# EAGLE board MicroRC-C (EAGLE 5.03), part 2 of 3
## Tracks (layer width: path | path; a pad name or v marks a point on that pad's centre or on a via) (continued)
CS_DTMF  (via drill 0.41) (continued)
  Top 0.178: U2.38 51.21,34.38 50.8,33.97 48.26,33.97 47.62,33.34 47.62,24.58 | v47.62,23.97 47.62,24.58 | v70.48,31.75 70.48,32.36 | 70.48,32.36 U6.10 | 47.62,24.58 47.35,24.14 v47.62,23.97 | 47.62,24.58 47.9,24.14 v47.62,23.97 | 70.48,32.36 70.21,31.92 v70.48,31.75 | 70.48,32.36 70.76,31.92 v70.48,31.75
  Bottom 0.178: 48.23,23.97 52.39,23.97 56.67,19.68 61.91,19.68 63.66,21.43 67.15,21.43 68.58,22.86 68.58,28.26 70.48,30.16 70.48,31.14 | 48.23,23.97 v47.62,23.97 | 70.48,31.14 v70.48,31.75 | 48.23,23.97 47.79,24.24 v47.62,23.97 | 48.23,23.97 47.79,23.7 v47.62,23.97 | 70.48,31.14 70.76,31.58 v70.48,31.75 | 70.48,31.14 70.21,31.58 v70.48,31.75
DISC_AUDIO
  Top 0.254: X3.6 144.46,58.42 146.05,56.83 146.05,49.21 146.72,48.54 R26.3 151.81,48.54 152.08,48.26 152.08,33.65 151.72,33.3 R27.3
  Bottom 0.61: X3.6 X3A.6
DTMF_Q1
  Top 0.178: 61.12,35.08 59.85,33.81 59.85,31.75 59.32,31.22 U2.29 | 61.12,35.08 | 61.12,35.08 71.6,35.08 71.75,34.92 U6.11
DTMF_Q2
  Top 0.178: U6.12 73.03,34.92 72.39,35.56 60.96,35.56 59.37,33.97 59.37,32.54 58.85,32.02 U2.30
DTMF_Q3
  Top 0.178: U6.13 74.3,34.92 73.18,36.04 60.8,36.04 58.9,34.13 58.9,33.34 58.38,32.82 U2.31
DTMF_Q4
  Top 0.178: U6.14 75.56,34.92 73.98,36.51 60.64,36.51 58.42,34.29 58.42,33.97 58.07,33.62 U2.32
EXP_IO0  (via drill 0.41)
  Top 0.178: v44.77,45.4 45.38,45.4 | 45.38,45.4 53.37,45.4 | 53.37,45.4 v53.98,45.4 | U2.4 45.61,24.55 45.09,25.08 45.09,27.01 | v45.09,27.62 45.09,27.01 | 53.37,45.4 53.81,45.13 v53.98,45.4 | 53.37,45.4 53.81,45.67 v53.98,45.4 | 45.09,27.01 45.36,27.46 v45.09,27.62 | 45.09,27.01 44.81,27.46 v45.09,27.62 | 45.38,45.4 44.93,45.67 v44.77,45.4 | 45.38,45.4 44.93,45.13 v44.77,45.4
  Bottom 0.178: v53.98,45.4 53.98,46.01 | 53.98,46.01 53.98,55.88 60.33,62.23 114.94,62.23 116.84,60.32 116.84,47.31 120.33,43.81 126.05,43.81 J2.15 | 45.09,28.23 45.09,33.34 44.13,34.29 44.13,43.81 44.77,44.45 44.77,44.79 | 45.09,28.23 v45.09,27.62 | 44.77,44.79 v44.77,45.4 | 53.98,46.01 53.7,45.57 v53.98,45.4 | 53.98,46.01 54.25,45.57 v53.98,45.4 | 45.09,28.23 44.81,27.79 v45.09,27.62 | 45.09,28.23 45.36,27.79 v45.09,27.62 | 44.77,44.79 45.04,45.24 v44.77,45.4 | 44.77,44.79 44.5,45.24 v44.77,45.4
EXP_IO1  (via drill 0.41)
  Top 0.178: v45.72,46.35 46.33,46.35 | 46.33,46.35 49.55,46.35 | 49.55,46.35 v50.16,46.35 | U2.5 46.41,24.71 46.04,25.08 46.04,26.06 | v46.04,26.67 46.04,26.06 | 49.55,46.35 50,46.08 v50.16,46.35 | 49.55,46.35 50,46.63 v50.16,46.35 | 46.04,26.06 46.31,26.5 v46.04,26.67 | 46.04,26.06 45.77,26.5 v46.04,26.67 | 46.33,46.35 45.88,46.63 v45.72,46.35 | 46.33,46.35 45.88,46.08 v45.72,46.35
  Bottom 0.178: J2.19 127.16,50.16 125.89,48.89 120.33,48.89 119.38,49.85 119.38,61.59 116.2,64.77 59.05,64.77 51.59,57.31 | 51.59,57.31 | 51.59,57.31 51.44,57.15 51.44,48.42 50.16,47.15 50.16,46.96 | v50.16,46.35 50.16,46.96 | v46.04,26.67 46.04,27.28 | 46.04,27.28 46.04,33.34 44.77,34.61 44.77,43.5 45.72,44.45 45.72,45.74 | 45.72,45.74 v45.72,46.35 | 50.16,46.96 49.89,46.52 v50.16,46.35 | 50.16,46.96 50.44,46.52 v50.16,46.35 | 46.04,27.28 45.77,26.84 v46.04,26.67 | 46.04,27.28 46.31,26.84 v46.04,26.67 | 45.72,45.74 45.99,46.19 v45.72,46.35 | 45.72,45.74 45.45,46.19 v45.72,46.35
EXP_IO2  (via drill 0.41)
  Top 0.178: U2.37 52.07,35.42 52.07,42.57 | 52.07,42.57 v52.07,43.18 | 52.07,42.57 52.34,43.01 v52.07,43.18 | 52.07,42.57 51.8,43.01 v52.07,43.18
  Bottom 0.178: v52.07,43.18 52.07,43.79 | 52.07,43.79 52.07,46.99 52.7,47.62 52.7,56.51 59.69,63.5 115.57,63.5 118.11,60.96 118.11,48.58 119.86,46.83 122.71,46.83 123.19,46.35 126.05,46.35 J2.17 | 52.07,43.79 51.8,43.35 v52.07,43.18 | 52.07,43.79 52.34,43.35 v52.07,43.18
EXT_COS  (via drill 0.41)
  Top 0.178: Q5.3 65.09,41.27 R18.1 62.23,40.96 59.98,40.96 | U2.34 54.41,40.44 54.81,40.84 | 54.81,40.84 v55.24,41.27 | v59.37,40.96 59.98,40.96 | 59.98,40.96 59.54,41.23 v59.37,40.96 | 59.98,40.96 59.54,40.69 v59.37,40.96 | 54.81,40.84 55.32,40.97 v55.24,41.27 | 54.81,40.84 54.94,41.35 v55.24,41.27
  Bottom 0.178: 58.76,40.96 57.78,40.96 57.47,41.27 55.85,41.27 | 58.76,40.96 v59.37,40.96 | v55.24,41.27 55.85,41.27 | 58.76,40.96 59.21,40.69 v59.37,40.96 | 58.76,40.96 59.21,41.23 v59.37,40.96 | 55.85,41.27 55.41,41.55 v55.24,41.27 | 55.85,41.27 55.41,41 v55.24,41.27
FAN
  Bottom 0.61: X3.2 X3A.2
  pour Top (isolate 0.61, rank 2, no thermals): 143.19,69.21 140.97,69.21 139.7,70.48 139.7,71.75 139.38,72.07 115.25,72.07 114.94,71.75 114.94,60.96 125.73,60.96 130.18,65.41 139.38,65.41 139.7,65.72 139.7,66.67 140.97,67.94 143.19,67.94
FAN_DRIVE  (via drill 0.41)
  Top 0.178: v63.5,46.35 63.5,46.96 | 63.5,46.96 R17.1 | U2.39 50.41,36.26 50.16,36.51 50.16,36.85 | 50.16,36.85 v50.16,37.46 | 63.5,46.96 63.23,46.52 v63.5,46.35 | 63.5,46.96 63.77,46.52 v63.5,46.35 | 50.16,36.85 50.44,37.3 v50.16,37.46 | 50.16,36.85 49.89,37.3 v50.16,37.46
  Bottom 0.178: 62.89,46.35 61.91,46.35 60.96,47.31 55.56,47.31 55.24,46.99 55.24,44.77 54.93,44.45 53.34,44.45 53.02,44.13 53.02,42.23 52.7,41.91 51.75,41.91 50.16,40.32 50.16,38.07 | 62.89,46.35 v63.5,46.35 | v50.16,37.46 50.16,38.07 | 62.89,46.35 63.33,46.08 v63.5,46.35 | 62.89,46.35 63.33,46.63 v63.5,46.35 | 50.16,38.07 49.89,37.63 v50.16,37.46 | 50.16,38.07 50.44,37.63 v50.16,37.46
GND  (via drill 0.41, 0.61)
  Top 0.178: C5.2 59.53,11.11 59.53,12.09 | 59.53,12.09 v59.53,12.7 | v83.98,42.23 | v83.98,42.23 | C12.1 15.53,13.97 | 15.53,13.97 v14.92,13.97 | U3.23 25.42,11.77 25.2,11.54 | 25.2,11.54 v24.77,11.11 | 59.53,12.09 59.8,12.53 v59.53,12.7 | 59.53,12.09 59.26,12.53 v59.53,12.7 | 15.53,13.97 15.09,14.24 v14.92,13.97 | 15.53,13.97 15.09,13.7 v14.92,13.97 | 25.2,11.54 24.69,11.42 v24.77,11.11 | 25.2,11.54 25.07,11.04 v24.77,11.11
  Top 0.254: U1.4 40.19,51.12 | 40.19,51.12 v40.8,51.12 | C9.2 49.87,54.93 | 49.87,54.93 v50.48,54.93 | 70.48,42.86 U6.9 | 75.56,42.86 U6.5 | U6.6 74.3,42.86 | U9.26 117.47,34.63 | 117.47,34.63 v117.47,35.24 | U2.22 58.2,25.62 58.31,25.51 | 58.31,25.51 v58.74,25.08 | U2.53 42.6,30.42 42.75,30.28 | v43.18,29.84 42.75,30.28 | U2.63 42.35,22.42 v42.86,21.91 | C7.2 64.77,29.21 65.76,29.21 | 65.76,29.21 v66.67,29.21 | 65.76,24.45 64.77,24.45 C6.2 | 65.76,24.45 v66.67,24.45 | v100.49,27.78 | C72.2 99.06,27.78 99.88,27.78 | 99.88,27.78 v100.49,27.78 | Q5.2 64.2,43.33 64.2,44.47 | 64.2,44.47 v64.2,45.08 | U8.12 85.09,42.23 84.59,42.23 | 84.59,42.23 v83.98,42.23 | U3.25 25.66,13.07 25.51,13.22 | 25.51,13.22 v25.08,13.65 | D2.A 69.37,41.27 69.53,41.43 69.53,42.25 | 69.53,42.25 v69.53,42.86 | 65.76,24.45 66.52,24.1 v66.67,24.45 | 65.76,24.45 66.52,24.79 v66.67,24.45 | 65.76,29.21 66.52,28.86 v66.67,29.21 | 65.76,29.21 66.52,29.56 v66.67,29.21 | 40.19,51.12 40.67,50.87 v40.8,51.12 | 40.19,51.12 40.67,51.37 v40.8,51.12 | 49.87,54.93 50.35,54.68 v50.48,54.93 | 49.87,54.93 50.35,55.18 v50.48,54.93 | 69.53,42.25 69.78,42.73 v69.53,42.86 | 69.53,42.25 69.28,42.73 v69.53,42.86 | 84.59,42.23 84.11,42.48 v83.98,42.23 84.11,41.98 84.59,42.23 | 99.88,27.78 100.36,27.53 v100.49,27.78 | 99.88,27.78 100.36,28.03 v100.49,27.78 | 64.2,44.47 64.45,44.96 v64.2,45.08 | 64.2,44.47 63.95,44.96 v64.2,45.08 | 117.47,34.63 117.72,35.11 v117.47,35.24 | 117.47,34.63 117.23,35.11 v117.47,35.24 | 58.31,25.51 58.47,25 v58.74,25.08 | 58.31,25.51 58.82,25.35 v58.74,25.08 | 42.75,30.28 42.91,29.76 v43.18,29.84 | 42.75,30.28 43.27,30.11 v43.18,29.84 | v42.86,21.91 42.6,21.82 42.43,22.34 42.95,22.17 v42.86,21.91
  Top 0.254: 25.51,13.22 25.35,13.74 v25.08,13.65 | 25.51,13.22 25,13.39 v25.08,13.65
  Top 0.406: 34.11,30.96 C2.2 | 34.11,30.96 v33.5,30.96 | v69.53,42.86 70.14,42.86 | 70.14,42.86 70.48,42.86 | 74.3,42.86 75.56,42.86 | U6.5 75.56,43.84 | 75.56,43.84 v75.56,44.45 | v116.2,40.96 116.2,41.57 | 116.2,41.57 U9.4 | U9.26 117.47,32.36 | 117.47,32.36 v117.47,31.75 | v79.06,26.67 79.67,26.67 | 79.67,26.67 81.28,26.67 C74.- | C22.2 32.09,11.11 | 32.09,11.11 v32.7,11.11 | 91.44,45.38 v91.44,44.77 | 91.44,45.38 C53.2 | 101.6,45.38 v101.6,44.77 | 101.6,45.38 C54.2 | C73.2 78.45,29.53 | 78.45,29.53 v79.06,29.53 | Q1.2 | 34.11,30.96 33.56,31.15 v33.5,30.96 | 34.11,30.96 33.56,30.76 v33.5,30.96 | 32.09,11.11 32.63,10.92 v32.7,11.11 | 32.09,11.11 32.63,11.3 v32.7,11.11 | 70.14,42.86 69.6,43.05 v69.53,42.86 | 70.14,42.86 69.6,42.67 v69.53,42.86 | 75.56,43.84 75.76,44.38 v75.56,44.45 | 75.56,43.84 75.37,44.38 v75.56,44.45 | 116.2,41.57 116.01,41.02 v116.2,40.96 | 116.2,41.57 116.4,41.02 v116.2,40.96 | 117.47,32.36 117.28,31.82 v117.47,31.75 | 117.47,32.36 117.67,31.82 v117.47,31.75 | 79.67,26.67 79.12,26.86 v79.06,26.67 | 79.67,26.67 79.12,26.48 v79.06,26.67 | 91.44,45.38 91.25,44.83 v91.44,44.77 | 91.44,45.38 91.63,44.83 v91.44,44.77 | 101.6,45.38 101.41,44.83 v101.6,44.77 | 101.6,45.38 101.79,44.83 v101.6,44.77 | 78.45,29.53 78.99,29.34 v79.06,29.53 | 78.45,29.53 78.99,29.72 v79.06,29.53
  Top 0.61: v62.87,15.24 C1.2 | Q2.3 42.95,48.49 41.91,49.53 v38.73,49.53 | v20.32,30.64 Q1.2
  Top 0.813: U4.4 118.43,48.1 | 118.43,48.1 U4.2 | 118.43,48.1
  Top 1.27: C3.- v71.12,20.95
  Bottom 0.254: J2.6 121.6,32.38 118.75,35.24 118.08,35.24 | v117.47,35.24 118.08,35.24 | 118.08,35.24 117.6,35.49 v117.47,35.24 | 118.08,35.24 117.6,34.99 v117.47,35.24
  other vias: 107.63,27.46 69.61,52.39 74.22,52.39 113.98,46.67 113.98,45.4 32.46,52.39 32.46,56.2 89.22,69.21 89.22,67.94 2.22,74.29
  pour GROUND (isolate 0.305, rank 2, no thermals): 0.95,75.88 0.95,52.7 5.71,52.7 6.03,52.39 6.03,49.85 5.71,49.53 0.95,49.53 0.95,0.95 69.22,0.95 69.22,11.11 arc-90 70.48,12.38 74.45,12.38 arc90 75.09,13.02 75.09,23.81 arc-90 76.36,25.08 82.23,25.08 arc90 82.87,25.72 82.87,27.62 arc-180 85.41,27.62 85.41,25.72 arc90 86.04,25.08 100.33,25.08 arc90 100.97,25.72 100.97,26.19 arc-90 102.23,27.46 111.76,27.46 arc90 112.39,28.1 112.39,31.75 arc-90 113.67,32.86 113.67,32.86 arc-90 114.94,31.59 114.94,28.89 arc90 115.57,28.26 121.6,28.26 arc90 122.24,28.89 122.24,30.48 arc-90 123.51,31.75 124.78,31.75 arc90 125.41,32.38 arc90 124.78,33.02 123.51,33.02 arc-90 122.24,34.29 122.24,46.51 arc90 121.6,47.15 113.98,47.15 arc90 113.35,46.2 113.35,44.45 arc-90 112.08,43.18 106.05,43.18 arc-90 104.78,44.45 104.78,46.35 arc90 104.14,46.99 81.92,46.99 arc-90 80.64,48.26 80.64,60.64 arc-90 81.92,61.91 91.76,61.91 arc90 92.39,62.55 92.39,75.88
  pour Top (isolate 0.406, no thermals): 62.55,25.4 62.55,28.26 66.04,28.26 66.04,30.32 70.64,30.32 70.64,23.34 66.04,23.34 66.04,25.4
  pour Top (isolate 0.406, no thermals): 28.26,56.67 28.26,51.91 34.92,51.91 34.92,56.67
  pour Top (isolate 0.406, no thermals): 69.06,46.99 74.77,46.99 74.77,57.15 69.06,57.15
  pour Top (isolate 0.61, no thermals): 120.17,44.77 109.22,44.77 109.22,47.62 114.3,47.62 114.62,47.94 114.62,50.16 114.94,50.48 120.17,50.48 120.17,48.58 121.76,48.58 121.76,47.62 120.17,47.62
  pour Bottom (isolate 0.61, rank 6, no thermals): 0.64,75.25 34.29,75.25 34.29,28.57 33.34,27.62 33.34,23.02 33.97,22.38 43.18,22.38 43.18,20.16 41.12,18.1 21.91,18.1 20.95,17.14 20.95,5.4 21.91,4.44 31.11,4.44 31.43,4.76 31.43,5.71 31.75,6.03 32.7,6.03 33.02,5.71 33.02,4.76 33.34,4.44 37.47,4.44 37.78,4.76 37.78,6.35 42.23,6.35 42.23,4.76 42.55,4.44 52.7,4.44 52.7,6.98 52.39,7.3 51.44,7.3 51.12,7.62 51.12,8.25 51.44,8.57 57.78,8.57 58.1,8.25 58.1,7.62 57.78,7.3 56.83,7.3 56.52,6.98 56.52,4.44 68.58,4.44 68.58,6.98 68.26,7.3 67.31,7.3 66.99,7.62 66.99,8.25 67.31,8.57 69.37,8.57 69.37,1.59 0.64,1.59 0.64,49.53 5.71,49.53 6.03,49.85 6.03,52.39 5.71,52.7 0.64,52.7
  pour Bottom (no thermals): 9.84,72.39 9.84,69.21 3.81,69.21 3.81,59.69 0.95,59.69 0.95,72.39
  pour Top (isolate 0.305, no thermals): 104.14,25.88 104.14,27.94 109.86,27.94 109.86,27.15 107.79,27.15 106.52,25.88
  pour Top (no thermals): 88.58,67.31 88.58,69.85 90.49,69.85 91.12,69.21 91.12,67.94 90.49,67.31
  pour Top (isolate 0.61, rank 6, no thermals): 0.95,75.25 0.95,1.59 69.22,1.59 69.22,8.89 66.67,8.89 66.67,6.98 67.63,6.98 67.94,6.67 67.94,2.86 67.31,2.22 44.45,2.22 42.55,4.13 42.55,6.35 37.78,6.35 37.78,3.49 37.47,3.17 33.34,3.17 33.02,3.49 33.02,6.03 31.43,6.03 31.43,4.13 30.8,3.49 14.61,3.49 13.97,4.13 13.97,10.16 6.99,10.16 5.71,11.43 5.71,20.95 6.67,20.95 6.67,23.81 7.62,24.76 9.53,24.76 10.48,25.72 13.65,25.72 13.65,40.64 12.22,40.64 11.11,41.75 11.11,58.74 3.49,58.74 2.86,59.37 2.86,68.26 3.49,68.9 11.75,68.9 11.75,75.25
I2C_SCL  (via drill 0.41)
  Top 0.178: v46.04,52.39 46.65,52.39 | 46.65,52.39 46.99,52.39 47.31,52.7 R10.1 | U2.25 57.01,27.94 55.54,27.94 | v54.93,27.94 55.54,27.94 | 45.43,52.39 v46.04,52.39 | 45.43,52.39 U1.6 | v49.37,49.53 49.98,49.53 | 49.98,49.53 50.48,49.53 51.12,50.16 54.32,50.16 | 54.32,50.16 v54.93,50.16 | 55.54,27.94 55.09,28.21 v54.93,27.94 | 55.54,27.94 55.09,27.67 v54.93,27.94 | 46.65,52.39 46.2,52.66 v46.04,52.39 | 46.65,52.39 46.2,52.12 v46.04,52.39 | 45.43,52.39 45.87,52.12 v46.04,52.39 | 45.43,52.39 45.87,52.66 v46.04,52.39 | 54.32,50.16 54.76,49.89 v54.93,50.16 | 54.32,50.16 54.76,50.44 v54.93,50.16 | 49.98,49.53 49.54,49.8 v49.37,49.53 | 49.98,49.53 49.54,49.26 v49.37,49.53
  Bottom 0.178: 54.32,27.94 48.26,27.94 47.62,28.57 47.62,40.32 46.51,41.43 46.51,48.74 46.04,49.21 46.04,51.78 | 54.32,27.94 v54.93,27.94 | 46.04,51.78 v46.04,52.39 | J2.13 126.05,41.27 123.19,41.27 122.56,41.91 117.47,41.91 116.2,43.18 116.2,60.01 114.62,61.59 60.64,61.59 54.93,55.88 54.93,50.77 | v54.93,50.16 54.93,50.77 | 49.37,50.14 49.37,51.91 48.9,52.39 46.65,52.39 | 49.37,50.14 v49.37,49.53 | v46.04,52.39 46.65,52.39 | 54.32,27.94 54.76,27.67 v54.93,27.94 | 54.32,27.94 54.76,28.21 v54.93,27.94 | 46.04,51.78 46.31,52.22 v46.04,52.39 | 46.04,51.78 45.77,52.22 v46.04,52.39 | 46.65,52.39 46.2,52.66 v46.04,52.39 | 46.65,52.39 46.2,52.12 v46.04,52.39 | 54.93,50.77 54.66,50.33 v54.93,50.16 | 54.93,50.77 55.2,50.33 v54.93,50.16 | 49.37,50.14 49.1,49.69 v49.37,49.53 | 49.37,50.14 49.64,49.69 v49.37,49.53
I2C_SDA  (via drill 0.41)
  Top 0.178: v47.15,49.53 47.15,50.14 | 47.15,50.14 47.15,51.12 | 55.11,49.21 51.28,49.21 50.8,48.74 47.31,48.74 47.15,48.89 47.15,48.92 | 55.11,49.21 v55.72,49.21 | v47.15,49.53 47.15,48.92 | U2.26 57.01,28.89 56.17,28.89 | v55.56,28.89 56.17,28.89 | 47.15,50.14 46.88,49.69 v47.15,49.53 | 47.15,50.14 47.42,49.69 v47.15,49.53 | 47.15,48.92 47.42,49.36 v47.15,49.53 | 47.15,48.92 46.88,49.36 v47.15,49.53 | 56.17,28.89 55.73,29.16 v55.56,28.89 | 56.17,28.89 55.73,28.62 v55.56,28.89 | 55.11,49.21 55.56,48.94 v55.72,49.21 | 55.11,49.21 55.56,49.48 v55.72,49.21
  Top 0.254: U1.5 47.15,51.12 R11.1
  Bottom 0.178: 54.95,28.89 48.58,28.89 48.26,29.21 48.26,40.64 47.15,41.75 47.15,48.92 | 54.95,28.89 v55.56,28.89 | J2.11 126.05,38.73 123.19,38.73 121.92,40 118.43,40 115.57,42.86 115.57,59.69 114.3,60.96 60.96,60.96 55.72,55.72 55.72,49.82 | v55.72,49.21 55.72,49.82 | v55.72,49.21 | 47.15,48.92 v47.15,49.53 | 47.15,48.92 47.42,49.36 v47.15,49.53 | 47.15,48.92 46.88,49.36 v47.15,49.53 | 54.95,28.89 55.4,28.62 v55.56,28.89 | 54.95,28.89 55.4,29.16 v55.56,28.89 | 55.72,49.82 55.45,49.38 v55.72,49.21 | 55.72,49.82 55.99,49.38 v55.72,49.21
INT_DTMF  (via drill 0.41)
  Top 0.178: v76.83,35.4 76.83,34.79 | 76.83,34.79 U6.15 | U2.6 47.23,19.82 47.23,21.61 | v47.23,22.22 47.23,21.61 | 76.83,34.79 77.11,35.24 v76.83,35.4 | 76.83,34.79 76.56,35.24 v76.83,35.4 | 47.23,21.61 47.5,22.06 v47.23,22.22 | 47.23,21.61 46.96,22.06 v47.23,22.22
  Bottom 0.178: 47.84,22.22 53.18,22.22 56.36,19.05 62.23,19.05 63.98,20.8 67.47,20.8 69.22,22.54 69.22,27.94 71.75,30.48 71.75,34.45 72.71,35.4 76.22,35.4 | 47.84,22.22 v47.23,22.22 | 76.22,35.4 v76.83,35.4 | 76.22,35.4 76.67,35.13 v76.83,35.4 | 76.22,35.4 76.67,35.67 v76.83,35.4 | 47.84,22.22 47.39,22.5 v47.23,22.22 | 47.84,22.22 47.39,21.95 v47.23,22.22
INT_EXP  (via drill 0.41)
  Top 0.178: v49.21,40.32 48.6,40.32 | 48.6,40.32 47.94,40.32 47.31,40.96 R79.1 | U2.27 56.1,29.62 55.88,29.84 55.54,29.84 | v54.93,29.84 55.54,29.84 | 55.54,29.84 55.09,30.12 v54.93,29.84 | 55.54,29.84 55.09,29.57 v54.93,29.84 | 48.6,40.32 49.05,40.05 v49.21,40.32 | 48.6,40.32 49.05,40.59 v49.21,40.32
  Bottom 0.178: J2.18 120.33,47.62 118.75,49.21 118.75,61.28 115.89,64.13 59.37,64.13 52.07,56.83 52.07,47.94 51.12,46.99 51.12,42.23 49.64,40.75 | v49.21,40.32 49.64,40.75 | 49.21,39.71 49.21,30.16 49.53,29.84 54.32,29.84 | 49.21,39.71 v49.21,40.32 | 54.32,29.84 v54.93,29.84 | 54.32,29.84 54.76,29.57 v54.93,29.84 | 54.32,29.84 54.76,30.12 v54.93,29.84 | 49.64,40.75 49.14,40.63 v49.21,40.32 | 49.64,40.75 49.52,40.25 v49.21,40.32 | 49.21,39.71 49.48,40.16 v49.21,40.32 | 49.21,39.71 48.94,40.16 v49.21,40.32
INT_ISD  (via drill 0.41)
  Top 0.178: v81.92,35.4 81.92,36.01 | 81.92,36.01 81.92,36.19 arc0 82.23,36.51 100.33,36.51 100.97,37.15 115.89,37.15 116.2,36.83 U9.25 | R69.1 113.67,30.32 113.82,30.48 114.62,30.48 116.2,32.07 U9.25 | U2.7 48.02,19.82 48.02,20.5 | v48.02,21.11 48.02,20.5 | 48.02,20.5 48.29,20.95 v48.02,21.11 | 48.02,20.5 47.75,20.95 v48.02,21.11 | 81.92,36.01 81.64,35.57 v81.92,35.4 | 81.92,36.01 82.19,35.57 v81.92,35.4
  Top 0.254: U9.25
  Bottom 0.178: 81.31,35.4 78.74,35.4 77.63,34.29 73.03,34.29 72.39,33.65 72.39,30.16 69.85,27.62 69.85,22.22 67.79,20.16 64.29,20.16 62.55,18.41 56.04,18.41 53.34,21.11 48.63,21.11 | 81.31,35.4 v81.92,35.4 | 48.63,21.11 v48.02,21.11 | 48.63,21.11 48.19,21.38 v48.02,21.11 | 48.63,21.11 48.19,20.84 v48.02,21.11 | 81.31,35.4 81.75,35.13 v81.92,35.4 | 81.31,35.4 81.75,35.67 v81.92,35.4
INT_MX828  (via drill 0.41)
  Top 0.178: U8.7 91.44,40.64 91.12,40.32 83.19,40.32 82.55,40.96 82.21,40.96 | v81.6,40.96 82.21,40.96 | 67.63,32.99 67.63,33.65 67.31,33.97 63.18,33.97 62.87,33.65 R50.2 61.59,32.38 59.63,30.42 U2.28 | 67.63,32.99 v67.63,32.38 | 82.21,40.96 81.76,41.23 v81.6,40.96 | 82.21,40.96 81.76,40.69 v81.6,40.96 | 67.63,32.99 67.36,32.55 v67.63,32.38 | 67.63,32.99 67.9,32.55 v67.63,32.38
  Bottom 0.178: 80.99,40.96 68.58,40.96 67.63,40 67.63,32.99 | 80.99,40.96 v81.6,40.96 | v67.63,32.38 67.63,32.99 | 80.99,40.96 81.43,40.69 v81.6,40.96 | 80.99,40.96 81.43,41.23 v81.6,40.96 | 67.63,32.99 67.36,32.55 v67.63,32.38 | 67.63,32.99 67.9,32.55 v67.63,32.38
ISD_RAC  (via drill 0.41)
  Top 0.178: v114.94,36.19 114.94,35.58 | 114.94,35.58 U9.24 114.94,31.75 114.14,30.96 111.76,30.96 111.44,30.64 R70.1 | U2.9 49.61,20.71 48.42,21.91 48.42,25.74 | v48.42,26.35 48.42,25.74 | 114.94,35.58 115.21,36.03 v114.94,36.19 | 114.94,35.58 114.66,36.03 v114.94,36.19 | 48.42,25.74 48.69,26.19 v48.42,26.35 | 48.42,25.74 48.15,26.19 v48.42,26.35
  Bottom 0.178: 114.94,36.8 114.94,59.37 113.98,60.32 61.28,60.32 56.52,55.56 56.52,50.32 57.31,49.53 64.14,49.53 65.09,48.58 65.09,43.5 62.87,41.27 62.87,33.02 62.23,32.38 59.37,32.38 58.74,31.75 58.74,26.99 58.1,26.35 49.03,26.35 | 114.94,36.8 v114.94,36.19 | v48.42,26.35 49.03,26.35 | 114.94,36.8 114.66,36.36 v114.94,36.19 | 114.94,36.8 115.21,36.36 v114.94,36.19 | 49.03,26.35 48.58,26.62 v48.42,26.35 | 49.03,26.35 48.58,26.08 v48.42,26.35
LCD_BKLITE  (via drill 0.41)
  Top 0.178: v45.72,43.18 45.11,43.18 | 45.11,43.18 R9.1 | v45.72,43.18 | U2.1 43.21,18.76 43.02,18.57 43.02,18.39 | v43.02,17.78 43.02,18.39 | 43.02,18.39 42.75,17.95 v43.02,17.78 | 43.02,18.39 43.29,17.95 v43.02,17.78 | 45.11,43.18 45.55,42.91 v45.72,43.18 | 45.11,43.18 45.55,43.45 v45.72,43.18
  Bottom 0.178: 45.72,42.57 45.72,41.27 46.99,40 46.99,26.03 46.67,25.72 43.02,25.72 42.7,25.4 42.7,23.81 44.13,22.38 44.13,18.1 43.81,17.78 43.63,17.78 | 45.72,42.57 v45.72,43.18 | 43.63,17.78 v43.02,17.78 | 43.63,17.78 43.19,18.05 v43.02,17.78 | 43.63,17.78 43.19,17.51 v43.02,17.78 | 45.72,42.57 45.99,43.01 v45.72,43.18 | 45.72,42.57 45.45,43.01 v45.72,43.18
LCD_E
  Top 0.178: J1.6 21.59,36.19 20.64,37.15 20.64,47.94 21.27,48.58 29.69,48.58 30.64,47.62 30.64,39.21 30.96,38.89 46.51,38.89 48.81,36.59 U2.41
LCD_RS
  Top 0.178: J1.4 20.16,36.35 20.16,48.1 21.11,49.05 29.84,49.05 31.11,47.78 31.11,39.53 31.27,39.37 46.99,39.37 49.61,36.75 U2.40
LCD_RW
  Top 0.178: J1.5 24.13,37.46 21.75,37.46 21.11,38.1 21.11,47.78 | 21.11,47.78 21.43,48.1 29.53,48.1 30.16,47.47 30.16,39.05 30.8,38.42 46.04,38.42 48.01,36.44 U2.42 | 21.11,47.78
LED_PWR  (via drill 0.41)
  Top 0.178: v38.73,33.18 38.12,33.18 | 38.12,33.18 R8.1 | v41.75,35.24 42.18,34.81 | 42.18,34.81 43.02,33.97 46.99,33.97 47.21,34.19 U2.43 | 38.12,33.18 38.57,32.91 v38.73,33.18 | 38.12,33.18 38.57,33.45 v38.73,33.18 | 42.18,34.81 42.06,35.32 v41.75,35.24 | 42.18,34.81 41.68,34.93 v41.75,35.24
  Bottom 0.178: v41.75,35.24 41.14,35.24 | 41.14,35.24 39.37,35.24 38.73,34.61 38.73,33.79 | 38.73,33.79 v38.73,33.18 | 38.73,33.79 38.46,33.34 v38.73,33.18 | 38.73,33.79 39.01,33.34 v38.73,33.18 | 41.14,35.24 41.59,34.97 v41.75,35.24 | 41.14,35.24 41.59,35.51 v41.75,35.24
MIX_BUSS
  Top 0.254: R72.1 R76.2 R59.2 136.84,11.75 136.53,12.06 134.94,12.06 | 134.94,12.06 132.72,12.06 132.4,11.75 C51.1 | 134.94,12.06 R64.2 134.94,14.92 134.62,15.24 128.27,15.24 127.95,15.56 R51.2
MIX_INSERT  (via drill 0.41)
  Top 0.254: 121.6,19.07 C47.1 121.6,15.56 121.28,15.24 114.94,15.24 114.62,14.92 R16.1 | 121.6,19.07 v121.6,19.68 | J2.4 126.05,28.57 126.05,26.17 | v126.05,25.56 126.05,26.17 | 126.05,26.17 125.8,25.69 v126.05,25.56 | 126.05,26.17 126.3,25.69 v126.05,25.56 | 121.6,19.07 121.85,19.56 v121.6,19.68 | 121.6,19.07 121.35,19.56 v121.6,19.68
  Bottom 0.254: 125.44,25.56 122.71,25.56 121.6,24.45 121.6,20.29 | 125.44,25.56 v126.05,25.56 | v121.6,19.68 121.6,20.29 | 125.44,25.56 125.92,25.31 v126.05,25.56 | 125.44,25.56 125.92,25.81 v126.05,25.56 | 121.6,20.29 121.35,19.81 v121.6,19.68 | 121.6,20.29 121.85,19.81 v121.6,19.68
MUTE_AUX
  Top 0.178: U7.7 114.62,22.54 114.3,22.86 114.3,24.45 114.62,24.76 121.28,24.76 122.08,25.56 122.08,36.99 121.28,37.78 119.06,37.78 118.75,38.1 100.33,38.1 99.69,37.46 60.33,37.46 57.94,35.08 56.36,35.08 53.66,32.38 53.66,23.97 55.21,22.42 U2.18
MUTE_RX
  Top 0.178: U7.3 112.71,21.27 113.03,21.59 113.03,24.61 113.67,25.24 121.13,25.24 121.6,25.72 121.6,36.83 121.13,37.31 118.9,37.31 118.59,37.62 100.65,37.62 100.01,36.99 60.48,36.99 58.1,34.61 56.52,34.61 54.13,32.23 54.13,24.29 55.2,23.22 U2.19
N$1
  pour Top (isolate 0.61, no thermals): 4.13,67.31 4.45,67.63 11.43,67.63 12.7,66.36 12.7,64.77 4.45,64.77 4.13,65.09
N$2
  Top 0.254: C8.1 38.73,26.99 39.05,26.67 39.05,24.13 39.96,23.22 U2.62
  Top 0.406: C8.1
N$3
  Top 0.254: R82.2 C45.1
N$4  (via drill 0.41)
  Top 0.254: R26.2 146.69,46.04 146.05,45.4 146.05,39.69 144.78,38.42 144.78,34.26 | v144.78,33.65 144.78,34.26 | C39.2 106.7,20 | 106.7,20 v107.31,20 | 144.78,34.26 144.53,33.78 v144.78,33.65 | 144.78,34.26 145.03,33.78 v144.78,33.65 | 106.7,20 107.19,19.75 v107.31,20 | 106.7,20 107.19,20.25 v107.31,20
  Bottom 0.254: v107.31,20 107.31,20.61 | 107.31,20.61 107.31,20.95 107.63,21.27 114.3,21.27 114.62,20.95 114.62,16.19 114.94,15.87 117.16,15.87 119.06,17.78 136.53,17.78 137.16,18.41 137.16,20.64 138.75,22.22 138.75,26.03 139.38,26.67 139.38,27.94 138.75,28.57 138.75,32.7 139.7,33.65 144.17,33.65 | 144.17,33.65 v144.78,33.65 | 144.17,33.65 144.65,33.41 v144.78,33.65 | 144.17,33.65 144.65,33.9 v144.78,33.65 | 107.31,20.61 107.07,20.13 v107.31,20 | 107.31,20.61 107.56,20.13 v107.31,20
N$5  (via drill 0.41)
  Top 0.254: v138.11,13.65 138.11,14.26 | 138.11,14.26 138.11,14.6 138.75,15.24 139.06,15.24 139.38,15.56 C58.1 | 114.62,20 R62.1 | v113.67,20 114.28,20 | 114.28,20 114.62,20 | U7.6 114.94,21.27 114.62,20.95 114.62,20 | 114.28,20 113.79,20.25 v113.67,20 | 114.28,20 113.79,19.75 v113.67,20 | 138.11,14.26 137.86,13.78 v138.11,13.65 | 138.11,14.26 138.36,13.78 v138.11,13.65
  Bottom 0.254: 137.68,13.22 137.16,12.7 113.98,12.7 113.67,13.02 113.67,19.39 | 137.68,13.22 v138.11,13.65 | 113.67,19.39 v113.67,20 | 113.67,19.39 113.91,19.87 v113.67,20 | 113.67,19.39 113.42,19.87 v113.67,20 | 137.68,13.22 138.2,13.39 v138.11,13.65 | 137.68,13.22 137.85,13.74 v138.11,13.65
N$6
  Top 0.254: R64.1 136.84,14.92 137.16,15.24 137.48,15.24 138.11,15.87 138.11,18.1 138.43,18.41 143.83,18.41 144.78,19.37 144.78,31.75 145.73,32.7 145.73,37.94 146.21,38.42 R63.2
N$7
  Top 0.254: R65.2 136.84,20.16 136.84,20.32 138.02,21.49 R66.2
N$8
  Top 0.254: C63.2 102.23,31.43 102.55,31.75 104.46,31.75 104.78,32.07 U9.16
N$9
  Top 0.254: JP5.2 R12.2
N$10
  Top 0.254: U8.11 86.36,44.13 86.04,44.45 84.14,44.45 83.82,44.77 C56.+
N$11
  Top 0.254: R83.2 C52.1
N$12
  Top 0.254: R42.2 92.71,21.91 93.34,21.27 95.25,21.27 95.89,20.64 JP4.1
N$13
  pour Top (isolate 0.61, rank 3, no thermals): 18.73,46.67 16.51,46.67 16.51,48.89 17.46,49.85 17.46,56.83 19.05,58.42 19.05,71.12 20.64,71.12 20.64,62.86 21.91,61.59 26.35,61.59 26.35,56.2 21.91,56.2 20.95,55.24 20.95,50.16 18.73,47.94
N$14
  pour Top (isolate 0.61, no thermals): 12.7,63.5 12.7,61.91 10.79,60.01 4.45,60.01 4.13,60.32 4.13,63.18 4.45,63.5
N$15  (via drill 0.41)
  Top 0.254: C59.1 133.06,16.83 | 133.06,16.83 v133.67,16.83 | 134.28,16.83 v133.67,16.83 | 134.28,16.83 R65.1 | v138.11,20 138.72,20 | 138.72,20 R67.1 C60.1 | 133.06,16.83 133.54,16.58 v133.67,16.83 | 133.06,16.83 133.54,17.08 v133.67,16.83 | 134.28,16.83 133.8,17.08 v133.67,16.83 | 134.28,16.83 133.8,16.58 v133.67,16.83 | 138.72,20 138.24,20.25 v138.11,20 | 138.72,20 138.24,19.75 v138.11,20
  Bottom 0.254: v133.67,16.83 134.28,16.83 | 134.28,16.83 136.84,16.83 138.11,18.1 138.11,19.39 | 138.11,19.39 v138.11,20 | v138.11,20 138.72,20 | 138.72,20 TP8.TP | 134.28,16.83 133.8,17.08 v133.67,16.83 | 134.28,16.83 133.8,16.58 v133.67,16.83 | 138.11,19.39 138.36,19.87 v138.11,20 | 138.11,19.39 137.86,19.87 v138.11,20 | 138.72,20 138.24,20.25 v138.11,20 | 138.72,20 138.24,19.75 v138.11,20
N$16
  Top 0.178: U6.7 73.18,42.86
  Top 0.254: U6.7 | 73.18,42.86 Y2.2
N$17
  Top 0.178: Y2.1 | Y2.1
  Top 0.254: U6.8 71.75,44.13 Y2.1
N$18
  Top 0.178: U6.4 76.83,41.27 76.99,41.12 80.49,41.12 80.64,41.27 U6.1
N$19
  pour Top (isolate 0.61, rank 3, no thermals): 22.23,72.07 29.84,72.07 30.16,71.75 30.16,68.26 30.48,67.94 33.02,67.94 33.02,65.41 33.34,65.09 33.34,62.86 22.54,62.86 21.91,63.5 21.91,71.75
N$20
  Top 0.254: Y4.2 37.15,54.93 U1.1
N$21
  Top 0.254: Y4.1 37.15,53.66 U1.2
N$22
  Top 0.254: C61.1 R68.2
N$23
  Top 0.254: R76.1 144.15,10.48 146.05,12.38 147.48,12.38 149.86,14.76 149.86,16.35 148,18.22 R75.2
N$24
  Top 0.254: 114.62,5.71 115.57,5.71 115.89,6.03 115.89,6.35 116.2,6.67 U10.12 | 114.62,5.71 108.58,5.71 108.27,5.4 C65.1 | 114.62,5.71 R77.2 | 114.62,5.71 R73.1
N$25  (via drill 0.41)
  Top 0.254: C64.2 119.72,16.83 | 119.72,16.83 v120.33,16.83 | 119.72,16.83 120.2,16.58 v120.33,16.83 | 119.72,16.83 120.2,17.08 v120.33,16.83
  Bottom 0.254: v120.33,16.83 120.94,16.83 | 120.94,16.83 126.36,16.83 127.32,15.87 141.6,15.87 141.92,16.19 141.92,24.13 143.47,25.68 R75.3 | 120.94,16.83 120.46,17.08 v120.33,16.83 | 120.94,16.83 120.46,16.58 v120.33,16.83
N$26
  Top 0.254: U6.2 79.38,44.45 80.33,45.4 R45.2 79.06,46.67 78.74,46.99 78.74,48.58 | 78.74,48.58 78.74,51.91 78.42,52.23 77.15,52.23 C40.2 | R41.2 77.15,48.42 77.31,48.58 78.74,48.58
N$27  (via drill 0.41)
  Top 0.254: v89.53,26.35 89.53,26.96 | 89.53,26.96 C41.2 | 89.53,26.96 89.29,26.48 v89.53,26.35 | 89.53,26.96 89.78,26.48 v89.53,26.35
  Bottom 0.254: 90.14,26.35 90.49,26.35 90.81,26.03 JP4.3 | 90.14,26.35 v89.53,26.35 | 90.14,26.35 89.66,26.6 v89.53,26.35 | 90.14,26.35 89.66,26.1 v89.53,26.35
N$28
  Top 0.254: U6.3 78.11,44.45 77.15,45.4 R41.1 76.83,46.99 76.04,46.99 75.72,47.31 75.72,50.16 76.04,50.48 C40.1
N$29
  Top 0.254: R32.2 73.5,27.62 73.66,27.78 73.66,29.37 arc0 73.82,29.53 C30.1 74.93,30.48 75.25,30.8 79.06,30.8 79.38,31.11 U6.17
N$30
  Top 0.254: 60.64,28.1 60.64,29.05 60.96,29.37 62.87,29.37 C7.1 | 60.64,28.1 Y1.1 | U2.24 59.77,27.22 60.64,28.1
N$31  (via drill 0.41)
  Top 0.254: v36.2,6.35 36.2,5.74 | 36.2,5.74 R14.2 | 36.2,5.74 36.44,6.22 v36.2,6.35 | 36.2,5.74 35.95,6.22 v36.2,6.35
  Bottom 0.178: JP5.4 41.27,9.52 40.96,9.84 36.51,9.84 36.2,9.52 36.2,6.96 | 36.2,6.96 v36.2,6.35 | 36.2,6.96 35.92,6.52 v36.2,6.35 | 36.2,6.96 36.47,6.52 v36.2,6.35
N$32
  Top 0.254: U6.16 78.11,31.91 77.79,31.59 72.71,31.59 72.39,31.27 R32.1
N$33  (via drill 0.41)
  Top 0.254: v106.05,31.75 106.05,32.36 | 106.05,32.36 U9.17 | C59.2 129.38,16.83 129.22,16.99 129.22,18.12 | v129.22,18.73 129.22,18.12 | 106.05,32.36 105.8,31.88 v106.05,31.75 | 106.05,32.36 106.29,31.88 v106.05,31.75 | 129.22,18.12 129.47,18.6 v129.22,18.73 | 129.22,18.12 128.97,18.6 v129.22,18.73
  Bottom 0.254: 128.61,18.73 117.16,18.73 116.52,19.37 116.52,27.94 115.25,29.21 106.68,29.21 106.05,29.84 106.05,31.14 | 128.61,18.73 v129.22,18.73 | 106.05,31.14 v106.05,31.75 | 106.05,31.14 106.29,31.62 v106.05,31.75 | 106.05,31.14 105.8,31.62 v106.05,31.75 | 128.61,18.73 129.09,18.48 v129.22,18.73 | 128.61,18.73 129.09,18.98 v129.22,18.73
N$34
  Top 0.178: U3.3 18.1,13.72 C12.2
N$35
  Top 0.254: C44.2 107.31,13.65 107,13.33 107,7.62 107.31,7.3 R48.1
N$36
  Top 0.178: U3.27 29.53,14.37 C11.2
N$37  (via drill 0.41)
  Top 0.254: v102.23,33.02 102.23,33.63 | 102.23,33.63 102.23,35.58 | 102.23,35.58 v102.23,36.19 | v115.89,16.83 116.5,16.83 | 116.5,16.83 C64.1 | 116.5,16.83 116.02,17.08 v115.89,16.83 | 116.5,16.83 116.02,16.58 v115.89,16.83 | 102.23,35.58 102.48,36.07 v102.23,36.19 | 102.23,35.58 101.99,36.07 v102.23,36.19 | 102.23,33.63 101.99,33.15 v102.23,33.02 | 102.23,33.63 102.48,33.15 v102.23,33.02
  Top 0.406: v104.78,40.96 104.78,41.57 | 104.78,41.57 U9.13 | 104.78,41.57 104.58,41.02 v104.78,40.96 | 104.78,41.57 104.97,41.02 v104.78,40.96
  Bottom 0.254: 102.23,32.41 102.23,27.62 103.19,26.67 114.94,26.67 115.89,25.72 115.89,17.44 | 102.23,32.41 v102.23,33.02 | 115.89,17.44 v115.89,16.83 | 104.17,40.96 103.5,40.96 102.23,39.69 102.23,36.8 | 104.17,40.96 v104.78,40.96 | v102.23,36.19 102.23,36.8 | 104.17,40.96 104.65,40.71 v104.78,40.96 | 104.17,40.96 104.65,41.21 v104.78,40.96 | 115.89,17.44 115.64,16.96 v115.89,16.83 | 115.89,17.44 116.14,16.96 v115.89,16.83 | 102.23,36.8 101.99,36.32 v102.23,36.19 | 102.23,36.8 102.48,36.32 v102.23,36.19 | 102.23,32.41 102.48,32.89 v102.23,33.02 | 102.23,32.41 101.99,32.89 v102.23,33.02
N$38
  Top 0.254: C6.1 62.87,24.29 60.96,24.29 60.64,24.61 Y1.2 60.64,25.56 59.78,26.42 U2.23
N$39
  Top 0.178: U3.1 20.58,16.89 20.32,17.14 C13.1
N$40
  Top 0.254: R45.1 C43.2
N$41
  Top 0.254: U8.10 C55.+
N$42
  Top 0.254: C48.2 R56.1
N$43  (via drill 0.41)
  Top 0.254: 97.79,11.75 97.79,10.79 97.47,10.48 U5.6 94.75,10.48 | 97.79,11.75 97.79,16.51 98.11,16.83 R36.2 | 97.79,11.75 U5.7 | v94.14,10.48 94.75,10.48 | R30.2 78.42,5.1 | 78.42,5.1 v78.42,5.71 | 94.75,10.48 94.27,10.73 v94.14,10.48 | 94.75,10.48 94.27,10.23 v94.14,10.48 | 78.42,5.1 78.67,5.59 v78.42,5.71 | 78.42,5.1 78.17,5.59 v78.42,5.71
  Bottom 0.254: 93.53,10.48 88.9,10.48 88.27,11.11 88.27,17.78 87.63,18.41 79.06,18.41 78.42,17.78 78.42,6.32 | 93.53,10.48 v94.14,10.48 | v78.42,5.71 78.42,6.32 | 93.53,10.48 94.01,10.23 v94.14,10.48 | 93.53,10.48 94.01,10.73 v94.14,10.48 | 78.42,6.32 78.17,5.84 v78.42,5.71 | 78.42,6.32 78.67,5.84 v78.42,5.71
N$44
  Top 0.178: U3.28 26.35,15.02 26.35,17.14 C10.1
N$45
  Top 0.178: U3.2 19.6,14.37 19.37,14.6 19.37,15.24 19.05,15.56 16.51,15.56 16.19,15.87 C13.2
N$46
  Top 0.178: U3.24 24.73,12.42 24.13,13.02 C10.2
N$47  (via drill 0.41)
  Top 0.254: C31.1 106.39,4.13 | 106.39,4.13 v107,4.13 | v142.88,2.86 143.49,2.86 | 143.49,2.86 150.5,2.86 152.08,4.44 152.08,29.84 151.13,30.8 R27.2 | 106.39,4.13 106.87,3.88 v107,4.13 | 106.39,4.13 106.87,4.38 v107,4.13 | 143.49,2.86 143,3.11 v142.88,2.86 | 143.49,2.86 143,2.61 v142.88,2.86
  Bottom 0.254: 142.26,2.86 107.31,2.86 107,3.17 107,3.52 | 142.26,2.86 v142.88,2.86 | v107,4.13 107,3.52 | 107,3.52 107.25,4 v107,4.13 | 107,3.52 106.75,4 v107,4.13 | 142.26,2.86 142.75,2.61 v142.88,2.86 | 142.26,2.86 142.75,3.11 v142.88,2.86
N$48
  Top 0.254: U7.2 108.58,22.54 108.27,22.22 R46.1 108.27,15.56 108.58,15.24 109.86,15.24 110.17,14.92 C44.1
N$49
  Top 0.254: R71.3 150.5,7.94 148.27,5.71 139.86,5.71 139.38,5.24 C62.1 139.38,2.86 139.06,2.54 75.25,2.54 74.61,3.17 74.61,13.33 74.93,13.65 C61.2
N$50
  Top 0.254: R71.2 146.69,7.94 146.05,7.3 R72.2
N$52
  Top 0.254: Y3.1 92.71,52.07 92.71,49.21 93.34,48.58 C53.1 R55.2 95.57,45.08 95.89,44.77 97.47,44.77 97.79,44.45 U8.2
N$53
  Top 0.254: Y3.2 100.33,52.07 100.33,49.21 99.69,48.58 C54.1 | C54.1 R55.1 | U8.1 99.06,44.45 99.69,45.08 C54.1
N$54
  Top 0.254: U8.19 R54.2 C49.2
N$55  (via drill 0.41)
  Top 0.254: U10.7 124.17,11.75 | 124.17,11.75 v124.78,11.75 | v124.78,11.75 125.39,11.75 | 125.39,11.75 125.73,11.75 126.05,12.06 R83.1 | v139.38,12.06 139.38,12.67 | 139.38,12.67 R53.2 | v138.11,7.3 137.5,7.3 | 137.5,7.3 R56.2 | 124.17,11.75 124.65,11.5 v124.78,11.75 | 124.17,11.75 124.65,12 v124.78,11.75 | 125.39,11.75 124.91,12 v124.78,11.75 | 125.39,11.75 124.91,11.5 v124.78,11.75 | 139.38,12.67 139.13,12.19 v139.38,12.06 | 139.38,12.67 139.63,12.19 v139.38,12.06 | 137.5,7.3 137.98,7.05 v138.11,7.3 | 137.5,7.3 137.98,7.55 v138.11,7.3
  Bottom 0.254: 138.77,12.06 138.11,12.06 137.79,11.75 136.84,11.75 | 138.77,12.06 v139.38,12.06 | v124.78,11.75 125.39,11.75 | 125.39,11.75 136.84,11.75 | 136.84,11.75 136.84,7.62 137.16,7.3 137.5,7.3 | 137.5,7.3 v138.11,7.3 | 125.39,11.75 124.91,12 v124.78,11.75 | 125.39,11.75 124.91,11.5 v124.78,11.75 | 138.77,12.06 139.25,11.82 v139.38,12.06 | 138.77,12.06 139.25,12.31 v139.38,12.06 | 137.5,7.3 137.98,7.05 v138.11,7.3 | 137.5,7.3 137.98,7.55 v138.11,7.3
N$56
  Top 0.254: R43.2 C39.1
N$57  (via drill 0.41)
  Top 0.254: U8.14 86.36,31.43 87.31,30.48 87.31,26.67 87,26.35 85.09,26.35 84.77,26.03 84.77,23.49 85.09,23.18 C46.2 R47.2 89.53,20.32 90.17,19.68 92.71,19.68 93.34,19.05 JP4.2 | v99.38,21.59 99.38,20.98 | 99.38,20.98 R43.1 | 99.38,20.98 99.63,21.46 v99.38,21.59 | 99.38,20.98 99.13,21.46 v99.38,21.59
  Bottom 0.254: 98.77,21.59 93.66,21.59 93.34,21.27 JP4.2 | 98.77,21.59 v99.38,21.59 | 98.77,21.59 99.25,21.34 v99.38,21.59 | 98.77,21.59 99.25,21.84 v99.38,21.59
N$58
  Top 0.254: C57.1 85.25,29.53 85.09,29.69 U8.13
N$59
  Top 0.254: U8.15 87.63,31.43 88.11,30.96 88.11,29.53 | 88.11,25.08 88.11,29.53 | C46.1 88.11,25.08 | 88.11,29.53 C41.1 | 88.11,25.08 R47.1 R42.1
N$60  (via drill 0.41)
  Top 0.254: U10.6 R60.2 126.05,9.21 126.36,8.89 130.49,8.89 | 130.49,8.89 137.5,8.89 | 137.5,8.89 v138.11,8.89 | 130.49,8.89 C48.1 | R52.1 148.55,11.11 146.69,11.11 144.46,8.89 143.49,8.89 | v142.88,8.89 143.49,8.89 | 137.5,8.89 137.98,8.64 v138.11,8.89 | 137.5,8.89 137.98,9.14 v138.11,8.89 | 143.49,8.89 143,9.14 v142.88,8.89 | 143.49,8.89 143,8.64 v142.88,8.89
  Bottom 0.254: v138.11,8.89 138.72,8.89 | 138.72,8.89 142.26,8.89 | 142.26,8.89 v142.88,8.89 | 138.72,8.89 138.24,9.14 v138.11,8.89 | 138.72,8.89 138.24,8.64 v138.11,8.89 | 142.26,8.89 142.75,8.64 v142.88,8.89 | 142.26,8.89 142.75,9.14 v142.88,8.89
N$61  (via drill 0.41)
  Top 0.254: C58.2 143.83,16.83 145.73,18.73 145.73,27.96 | 145.73,27.96 v145.73,28.57 | v145.73,28.57 145.73,29.18 | 145.73,29.18 145.73,31.43 146.69,32.38 146.69,34.61 150.5,38.42 R63.3 150.5,40.96 | 145.73,27.96 145.98,28.45 v145.73,28.57 | 145.73,27.96 145.48,28.45 v145.73,28.57 | 145.73,29.18 145.48,28.7 v145.73,28.57 | 145.73,29.18 145.98,28.7 v145.73,28.57
  Bottom 0.254: R66.3 142.08,29.05 142.56,28.57 145.12,28.57 | v145.73,28.57 145.12,28.57 | 145.12,28.57 145.6,28.33 v145.73,28.57 | 145.12,28.57 145.6,28.82 v145.73,28.57
N$62  (via drill 0.41)
  Top 0.254: v133.67,10.48 134.28,10.48 | 134.28,10.48 R59.1 | 102.55,23.18 C50.2 | 134.28,10.48 133.8,10.73 v133.67,10.48 | 134.28,10.48 133.8,10.23 v133.67,10.48
  Top 0.406: v102.55,21.59 102.55,22.2 | 102.55,22.2 102.55,23.18 | 102.55,22.2 102.36,21.66 v102.55,21.59 | 102.55,22.2 102.74,21.66 v102.55,21.59
  Bottom 0.254: 102.55,20.98 102.55,18.41 103.19,17.78 112.08,17.78 112.39,17.46 112.39,11.11 113.03,10.48 133.06,10.48 | 102.55,20.98 v102.55,21.59 | 133.06,10.48 v133.67,10.48 | 102.55,20.98 102.8,21.46 v102.55,21.59 | 102.55,20.98 102.3,21.46 v102.55,21.59 | 133.06,10.48 133.54,10.23 v133.67,10.48 | 133.06,10.48 133.54,10.73 v133.67,10.48
N$63
  Top 0.254: U1.3 41.91,52.39 42.23,52.07 42.23,50.8 43.18,49.85 44.29,49.85 44.61,49.53 44.61,47.78 45.24,47.15 56.67,47.15 57.15,46.67 57.15,44.13 57.78,43.5 B1.+
N$64
  Top 0.254: C33.1 C32.2 R33.2
N$65
  pour Bottom (no thermals): 65.88,58.9 72.71,58.9 72.71,56.67 65.88,56.67
N$66  (via drill 0.41)
  Top 0.178: R15.2 60.33,50.82 | 60.33,50.82 v60.33,51.43 | Q3.1 105.73,54.61 104.11,54.61 | v103.5,54.61 104.11,54.61 | 60.33,50.82 60.6,51.27 v60.33,51.43 | 60.33,50.82 60.05,51.27 v60.33,51.43 | 104.11,54.61 103.67,54.88 v103.5,54.61 | 104.11,54.61 103.67,54.34 v103.5,54.61
  Bottom 0.178: 102.89,54.61 102.23,54.61 101.6,55.24 65.41,55.24 64.77,54.61 64.77,53.02 64.45,52.7 60.64,52.7 60.33,52.39 60.33,52.04 | 102.89,54.61 v103.5,54.61 | v60.33,51.43 60.33,52.04 | 60.33,52.04 60.05,51.6 v60.33,51.43 | 60.33,52.04 60.6,51.6 v60.33,51.43 | 102.89,54.61 103.34,54.34 v103.5,54.61 | 102.89,54.61 103.34,54.88 v103.5,54.61
N$67
  Top 0.178: R9.2 41.59,44.13 41.91,44.45 42.86,44.45 43.02,44.61 Q2.1
N$68
  Top 0.61: Q2.2 Q2.4 38.42,46.99 37.47,47.94 X4.2
N$69
  Top 0.813: X4.1 33.02,45.4 32.7,45.08 R6.2
N$70
  Top 0.254: R34.1 80.96,14.92 81.28,15.24 87,15.24 87.31,14.92 R29.2 88.58,13.65 88.9,13.33 88.9,12.06 89.22,11.75 U5.8
N$72
  Top 0.254: U5.9 R39.1 87.31,11.75 87,12.06 82.87,12.06 | 82.87,12.06 R34.2 | C36.2 82.87,12.06
N$73
  Top 0.254: U8.17 90.17,31.43 90.81,30.8 90.81,26.67 91.12,26.35 93.98,26.35 94.3,26.03 94.3,23.49 94.61,23.18 R57.1
N$76  (via drill 0.41)
  Top 0.254: R19.1 66.36,47.94 66.36,45.69 | v66.36,45.08 66.36,45.69 | v66.36,45.08 66.97,45.08 | 66.97,45.08 D2.C | Q5.1 66.36,43.33 66.36,44.47 | 66.36,44.47 v66.36,45.08 | 66.36,45.69 66.11,45.21 v66.36,45.08 | 66.36,45.69 66.61,45.21 v66.36,45.08 | 66.97,45.08 66.49,45.33 v66.36,45.08 | 66.97,45.08 66.49,44.84 v66.36,45.08 | 66.36,44.47 66.61,44.96 v66.36,45.08 | 66.36,44.47 66.11,44.96 v66.36,45.08
N$77
  Top 0.254: R30.1 C35.1
N$78
  pour Top (isolate 0.61, rank 2, no thermals): 18.41,41.59 12.7,41.59 12.06,42.23 12.06,52.7 12.7,53.34 16.51,53.34 16.51,50.16 14.61,50.16 13.97,49.53 13.97,44.77 14.61,44.13 18.41,44.13
N$79  (via drill 0.41)
  Top 0.178: 63.5,50.82 R17.2 | 63.5,50.82 v63.5,51.43 | 63.5,50.82 63.77,51.27 v63.5,51.43 | 63.5,50.82 63.23,51.27 v63.5,51.43
  Top 0.254: v113.98,56.51 114.59,56.51 | 114.59,56.51 118.11,56.51 Q4.1 | 114.59,56.51 114.11,56.76 v113.98,56.51 | 114.59,56.51 114.11,56.27 v113.98,56.51
  Bottom 0.178: 113.98,55.9 113.98,53.97 113.67,53.66 102.23,53.66 101.28,54.61 66.04,54.61 65.72,54.29 65.72,51.75 65.41,51.43 64.11,51.43 | 113.98,55.9 v113.98,56.51 | v63.5,51.43 64.11,51.43 | 64.11,51.43 63.66,51.71 v63.5,51.43 | 64.11,51.43 63.66,51.16 v63.5,51.43 | 113.98,55.9 114.25,56.35 v113.98,56.51 | 113.98,55.9 113.71,56.35 v113.98,56.51
N$80
  Top 0.254: U8.21 95.25,31.11 95.57,30.8 97.16,30.8 97.47,30.48 97.47,26.67 97.79,26.35 100.33,26.35 100.65,26.03 100.65,23.49 100.33,23.18 R58.1
N$81
  pour Top (isolate 0.61, no thermals): 14.92,63.5 17.14,63.5 17.78,62.86 17.78,59.05 16.51,57.78 12.7,57.78 12.7,60.64 13.97,61.91 13.97,66.83 13.97,66.99 13.34,67.63 12.7,67.63 12.7,69.53 14.61,69.53 14.61,66.83 14.61,63.82
N$82
  Top 0.254: 99.38,8.89 98.42,8.89 98.11,9.21 U5.5 | 99.38,8.89 C34.2 | 99.38,8.89 100.97,8.89 101.28,8.57 R24.2
N$83
  Top 0.254: R52.2 148,14.01 147.64,13.65 R53.1
  Bottom 0.254: R52.2 148,17.5 148.55,18.06 R52.3
N$84
  Top 0.254: U9.14 103.5,49.53 103.82,49.85 C67.+
N$85
  Top 0.254: U10.9 116.2,10.48 115.89,10.16 115.89,9.21 115.57,8.89 112.71,8.89 | 110.17,8.89 112.71,8.89 | 110.17,8.89 R48.2 | 112.71,8.89 R44.1 | 110.17,8.89 108.58,8.89 108.27,9.21 C42.1
N$86  (via drill 0.41, 0.61)
  Top 0.61: U12.3 | U12.3 | U12.3 38.26,19.37 v36.83,19.37 C79.+
  SUPPLY 0.406: 37.44,19.37 55.56,19.37 56.2,18.73 63.85,18.73 | 37.44,19.37 v36.83,19.37 | 63.85,18.73 v64.77,18.73 | 37.44,19.37 36.9,19.56 v36.83,19.37 | 37.44,19.37 36.9,19.18 v36.83,19.37 | 63.85,18.73 64.67,18.44 v64.77,18.73 | 63.85,18.73 64.67,19.02 v64.77,18.73
  pour Top (no thermals): 62.71,21.59 64.29,21.59 64.61,21.91 66.83,21.91 66.83,16.19 64.45,16.19 64.14,16.51 64.14,20 63.82,20.32 62.71,20.32
N$87
  Top 0.254: 114.62,12.06 R44.2 | 114.62,12.06 115.89,12.06 116.2,11.75 117.16,11.75 | 117.16,11.75 U10.8 | C42.2 110.17,11.75 110.49,12.06 114.62,12.06 | 117.16,11.75 R82.1
N$88
  Top 0.254: C34.1 101.28,11.75 100.97,12.06 99.69,12.06 99.38,12.38 C33.2 99.38,14.92 99.69,15.24 100.97,15.24 101.28,15.56 R36.1
N$89
  Top 0.254: R58.2 R57.2 C49.1 R54.1 91.6,27.62 91.44,27.78 U8.18
N$90  (via drill 0.41)
  Top 0.406: v8.26,51.12 7.64,51.12 | 7.64,51.12 D11.K | 7.64,51.12 8.19,50.93 v8.26,51.12 | 7.64,51.12 8.19,51.31 v8.26,51.12
  Top 0.61: Q1.3 | v14.92,29.69 Q1.3
  Bottom 0.406: v8.26,51.12 8.26,50.51 | 8.26,50.51 8.26,40.96 13.65,35.56 13.65,30.16 14.13,29.69 14.31,29.69 | 14.31,29.69 v14.92,29.69 | 14.31,29.69 14.86,29.49 v14.92,29.69 | 14.31,29.69 14.86,29.88 v14.92,29.69 | 8.26,50.51 8.45,51.05 v8.26,51.12 | 8.26,50.51 8.06,51.05 v8.26,51.12
N$91  (via drill 0.41)
  Top 0.406: v8.26,52.7 7.64,52.7 | 7.64,52.7 2.06,52.7 1.75,52.39 D11.A | 7.64,52.7 8.19,52.51 v8.26,52.7 | 7.64,52.7 8.19,52.9 v8.26,52.7
  Top 0.61: v14.76,33.65 R7.2
  Bottom 0.406: v8.26,52.7 8.69,52.27 | 8.69,52.27 9.21,51.75 9.21,41.27 14.76,35.72 14.76,34.26 | 14.76,34.26 v14.76,33.65 | 14.76,34.26 14.57,33.72 v14.76,33.65 | 14.76,34.26 14.96,33.72 v14.76,33.65 | 8.69,52.27 8.44,52.79 v8.26,52.7 | 8.69,52.27 8.17,52.52 v8.26,52.7
N$92
  Top 0.178: R8.2 29.69,33.18 27.94,34.92 24.45,34.92 24.13,34.61 24.13,29.21 23.66,28.74 Q1.1
N$93
  Top 0.254: C47.2 R51.1
N$94  (via drill 0.41)
  Top 0.254: v102.55,7.3 103.16,7.3 | 103.16,7.3 C29.2 R25.2 103.82,11.75 104.14,12.06 105.41,12.06 105.73,12.38 C32.1 | U5.1 97.18,4.13 | 97.18,4.13 v97.79,4.13 | 103.16,7.3 102.68,7.55 v102.55,7.3 | 103.16,7.3 102.68,7.05 v102.55,7.3 | 97.18,4.13 97.66,3.88 v97.79,4.13 | 97.18,4.13 97.66,4.38 v97.79,4.13
  Bottom 0.254: 102.55,6.69 102.55,4.44 102.23,4.13 98.4,4.13 | 102.55,6.69 v102.55,7.3 | v97.79,4.13 98.4,4.13 | 102.55,6.69 102.8,7.17 v102.55,7.3 | 102.55,6.69 102.3,7.17 v102.55,7.3 | 98.4,4.13 97.92,4.38 v97.79,4.13 | 98.4,4.13 97.92,3.88 v97.79,4.13
N$95
  Top 0.254: U5.10 89.22,9.21 88.9,8.89 80.96,8.89 | 80.96,8.89 C36.1 | R38.1 76.52,9.21 76.83,8.89 78.42,8.89 | C35.2 78.42,8.89 | 78.42,8.89 80.96,8.89
N$96  (via drill 0.41)
  Top 0.254: C37.1 83.53,7.3 | 83.53,7.3 v84.14,7.3 | v84.14,7.3 84.75,7.3 | 84.75,7.3 C38.2 85.41,6.35 85.72,6.03 88.58,6.03 89.22,6.67 U5.12 | v84.14,13.65 84.75,13.65 | 84.75,13.65 R29.1 | 83.53,7.3 84.01,7.05 v84.14,7.3 | 83.53,7.3 84.01,7.55 v84.14,7.3 | 84.75,7.3 84.27,7.55 v84.14,7.3 | 84.75,7.3 84.27,7.05 v84.14,7.3 | 84.75,13.65 84.27,13.9 v84.14,13.65 | 84.75,13.65 84.27,13.4 v84.14,13.65
  Bottom 0.254: 83.53,13.65 83.5,13.65 83.19,13.33 83.19,7.62 83.5,7.3 83.53,7.3 | 83.53,13.65 v84.14,13.65 | v84.14,7.3 83.53,7.3 | 83.53,7.3 84.01,7.05 v84.14,7.3 | 83.53,7.3 84.01,7.55 v84.14,7.3 | 83.53,13.65 84.01,13.4 v84.14,13.65 | 83.53,13.65 84.01,13.9 v84.14,13.65
N$98
  Top 0.254: R25.1 C29.1 105.73,6.03 105.41,5.71 99.38,5.71 | 99.38,5.71 98.11,5.71 97.79,5.4 U5.2 | 99.38,5.71 R28.2
N$99
  Top 0.254: R28.1 C31.2
N$102
  Top 0.254: 82.87,5.4 R40.1 | 82.87,5.4 85.41,5.4 | 85.41,5.4 U5.13 | 82.87,5.4 81.28,5.4 80.96,5.71 C37.2 | 85.41,5.4 R35.2
N$105  (via drill 0.41)
  Top 0.178: R1.1 51.75,10.61 | 51.75,10.61 v51.75,10 | 51.75,10.61 51.48,10.17 v51.75,10 | 51.75,10.61 52.02,10.17 v51.75,10
  Bottom 0.178: JP2.1 45.09,5.4 44.77,5.71 44.77,9.52 45.24,10 51.14,10 | v51.75,10 51.14,10 | 51.14,10 51.59,9.73 v51.75,10 | 51.14,10 51.59,10.27 v51.75,10
N$106
  Top 0.254: R60.1 C51.2
N$107
  Top 0.178: R4.1 54.29,9.84 | JP2.3 50.48,6.67 53.98,6.67 54.29,6.98 54.29,9.84 | 54.29,9.84
N$108
  Top 0.178: R3.1 JP2.4
N$109
  Top 0.254: 127.95,5.71 125.41,5.71 124.46,6.67 U10.3 | 127.95,5.71 130.49,5.71 | 127.95,5.71 R78.2 | 130.49,5.71 R74.1 | C66.1 135.25,4.13 135.25,5.4 134.94,5.71 130.49,5.71
N$111  (via drill 0.41)
  Top 0.254: v88.58,4.13 89.19,4.13 | 89.19,4.13 U5.14 | R35.1 87.97,4.13 | 87.97,4.13 v88.58,4.13 | v79.69,16.83 80.3,16.83 | 80.3,16.83 R31.2 | 89.19,4.13 88.71,4.38 v88.58,4.13 | 89.19,4.13 88.71,3.88 v88.58,4.13 | 87.97,4.13 88.45,3.88 v88.58,4.13 | 87.97,4.13 88.45,4.38 v88.58,4.13 | 80.3,16.83 79.82,17.08 v79.69,16.83 | 80.3,16.83 79.82,16.58 v79.69,16.83
  Bottom 0.254: 80.3,16.83 86.04,16.83 86.68,16.19 86.68,4.76 R35.1 87.97,4.13 | 80.3,16.83 v79.69,16.83 | v88.58,4.13 87.97,4.13 | 87.97,4.13 88.45,3.88 v88.58,4.13 | 87.97,4.13 88.45,4.38 v88.58,4.13 | 80.3,16.83 79.82,17.08 v79.69,16.83 | 80.3,16.83 79.82,16.58 v79.69,16.83
PA0
  Top 0.178: 26.19,37.94 29.53,34.61 38.73,34.61 | J1.7 | 26.19,37.94 | 26.19,37.94 J1.7 | U2.51 40.05,32.02 39.69,32.38 39.69,34.29 39.37,34.61 38.73,34.61 | 38.73,34.61
PA1
  Top 0.178: J1.8 | J1.8 24.13,40 26.51,40 26.83,39.69 26.83,37.94 29.69,35.08 39.21,35.08 | U2.50 40.52,32.82 40.32,33.02 40.32,34.61 39.85,35.08 39.21,35.08 | 39.21,35.08
PA2
  Top 0.178: J1.9 | J1.9 26.99,41.27 27.3,40.96 27.3,38.1 29.84,35.56 40.32,35.56 41.41,34.47 U2.49
PA3
  Top 0.178: J1.10 | J1.10 24.13,42.54 27.46,42.54 27.78,42.23 27.78,38.26 30,36.04 42.07,36.04 42.68,35.42 U2.48
PA4
  Top 0.178: J1.11 27.94,43.81 28.26,43.5 28.26,38.42 30.16,36.51 43.81,36.51 44.01,36.31 U2.47
PA5
  Top 0.178: J1.12 | J1.12 24.13,45.08 28.42,45.08 28.73,44.77 28.73,38.58 30.32,36.99 44.45,36.99 44.81,36.63 U2.46
PA6
  Top 0.178: J1.13 | J1.13 28.73,46.35 29.21,45.88 29.21,38.73 30.48,37.46 44.93,37.46 45.61,36.78 U2.45
PA7
  Top 0.178: J1.14 | J1.14 22.86,47.31 23.18,47.62 29.37,47.62 29.69,47.31 29.69,38.89 30.64,37.94 45.4,37.94 46.41,36.93 U2.44
PTT
  Bottom 0.61: X3.1 X3A.1
  pour Top (isolate 0.61, rank 3, no thermals): 102.87,60.96 102.87,75.25 143.19,75.25 143.19,70.8 140.65,70.8 140.65,72.07 140.02,72.71 114.62,72.71 113.98,72.07 113.98,60.96
PTT_DRIVE  (via drill 0.41)
  Top 0.178: v60.33,46.35 60.33,46.96 | 60.33,46.96 R15.1 | U2.36 52.81,41.06 53.98,42.23 53.98,42.89 | 53.98,42.89 v53.98,43.5 | 60.33,46.96 60.05,46.52 v60.33,46.35 | 60.33,46.96 60.6,46.52 v60.33,46.35 | 53.98,42.89 54.25,43.33 v53.98,43.5 | 53.98,42.89 53.7,43.33 v53.98,43.5
  Bottom 0.178: v53.98,43.5 54.59,43.5 | 54.59,43.5 55.88,43.5 56.2,43.81 56.2,46.04 56.52,46.35 59.72,46.35 | 59.72,46.35 v60.33,46.35 | 59.72,46.35 60.16,46.08 v60.33,46.35 | 59.72,46.35 60.16,46.63 v60.33,46.35 | 54.59,43.5 54.14,43.77 v53.98,43.5 | 54.59,43.5 54.14,43.23 v53.98,43.5
RESET
  Top 0.178: JP1.6 62.55,9.37 62.23,9.68 57.31,9.68 | 57.31,9.68 55.56,9.68 55.24,9.37 55.24,5.71 54.93,5.4 JP2.5 | C5.1 57.31,9.68 | U2.20 58.21,24.02 58.42,23.81 58.42,20 57.31,18.89 R5.1 57.31,14.6 | C5.1 57.15,11.11 57.16,11.12 | 57.31,14.6 D1.A | 57.31,14.6 C5.1
RX_AUDIO_OUT  (via drill 0.41)
  Top 0.254: v88.9,31.75 88.9,32.36 | 88.9,32.36 U8.16 | v93.98,31.75 93.98,32.36 | 93.98,32.36 U8.20 | v82.55,43.18 82.55,43.79 | 82.55,43.79 82.55,44.13 81.92,44.77 81.92,52.07 81.6,52.39 C43.1 TP6.TP | 88.9,32.36 88.65,31.88 v88.9,31.75 | 88.9,32.36 89.15,31.88 v88.9,31.75 | 93.98,32.36 93.73,31.88 v93.98,31.75 | 93.98,32.36 94.23,31.88 v93.98,31.75 | 82.55,43.79 82.3,43.31 v82.55,43.18 | 82.55,43.79 82.8,43.31 v82.55,43.18
  Bottom 0.254: 88.9,34.29 93.98,34.29 | 88.9,34.29 86.04,34.29 85.72,34.61 85.72,42.86 85.41,43.18 83.16,43.18 | 88.9,32.36 88.9,34.29 | 88.9,32.36 v88.9,31.75 | 93.98,34.29 93.98,32.36 | 93.98,32.36 v93.98,31.75 | 93.98,34.29 106.68,34.29 107.31,33.65 117.79,33.65 119.06,32.38 119.06,29.21 119.7,28.57 126.05,28.57 J2.1 | 83.16,43.18 v82.55,43.18 | 88.9,32.36 88.65,31.88 v88.9,31.75 | 88.9,32.36 89.15,31.88 v88.9,31.75 | 93.98,32.36 93.73,31.88 v93.98,31.75 | 93.98,32.36 94.23,31.88 v93.98,31.75 | 83.16,43.18 82.68,43.43 v82.55,43.18 | 83.16,43.18 82.68,42.93 v82.55,43.18
RX_AUDIO_RET  (via drill 0.41)
  Top 0.254: U7.5 118.45,20 | 118.45,20 v119.06,20 | 118.45,20 118.93,19.75 v119.06,20 | 118.45,20 118.93,20.25 v119.06,20
  Bottom 0.254: v119.06,20 119.06,20.61 | 119.06,20.61 119.06,26.67 119.7,27.3 J2.2 | 119.06,20.61 118.81,20.13 v119.06,20 | 119.06,20.61 119.31,20.13 v119.06,20
SPI_MISO  (via drill 0.41)
  Top 0.178: v93.98,40 93.98,40.61 | 93.98,40.61 U8.5 | v93.98,40 93.5,39.53 93.34,39.37 56.81,39.37 | v93.98,40 | v56.2,39.37 56.81,39.37 | v98.58,40 99.19,40 | 99.19,40 116.84,40 117.47,40.64 117.47,42.54 | 117.47,42.54 U9.3 | 117.47,42.54 117.47,43.84 | 117.47,43.84 v117.47,44.45 | 51.59,32.57 51.59,22.38 52.81,21.16 U2.13 | 51.59,32.57 v51.59,33.18 | 93.98,40.61 93.71,40.17 v93.98,40 | 93.98,40.61 94.25,40.17 v93.98,40 | v93.98,40 94.06,39.7 93.55,39.57 93.67,40.08 v93.98,40 | 56.81,39.37 56.36,39.64 v56.2,39.37 | 56.81,39.37 56.36,39.1 v56.2,39.37 | 51.59,32.57 51.87,33.01 v51.59,33.18 | 51.59,32.57 51.32,33.01 v51.59,33.18 | 99.19,40 98.75,40.28 v98.58,40 | 99.19,40 98.75,39.73 v98.58,40 | 117.47,43.84 117.75,44.28 v117.47,44.45 | 117.47,43.84 117.2,44.28 v117.47,44.45
  Bottom 0.178: v93.98,40 94.59,40 | 94.59,40 97.97,40 | 97.97,40 v98.58,40 | 55.59,39.37 53.18,39.37 52.7,38.89 52.7,33.5 52.39,33.18 52.2,33.18 | 55.59,39.37 v56.2,39.37 | v51.59,33.18 52.2,33.18 | J2.14 123.19,42.54 122.87,42.86 118.11,42.86 117.47,43.5 117.47,43.84 | v117.47,44.45 117.47,43.84 | 94.59,40 94.14,40.28 v93.98,40 | 94.59,40 94.14,39.73 v93.98,40 | 55.59,39.37 56.03,39.1 v56.2,39.37 | 55.59,39.37 56.03,39.64 v56.2,39.37 | 52.2,33.18 51.76,33.45 v51.59,33.18 | 52.2,33.18 51.76,32.91 v51.59,33.18 | 97.97,40 98.42,39.73 v98.58,40 | 97.97,40 98.42,40.28 v98.58,40 | 117.47,43.84 117.75,44.28 v117.47,44.45 | 117.47,43.84 117.2,44.28 v117.47,44.45
SPI_MOSI  (via drill 0.41)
